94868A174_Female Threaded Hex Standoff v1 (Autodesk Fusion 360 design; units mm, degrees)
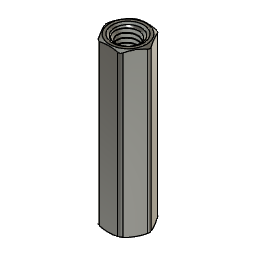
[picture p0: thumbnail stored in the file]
description: STEP AP203
part number: 94868A174_Female Threaded Hex Standoff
